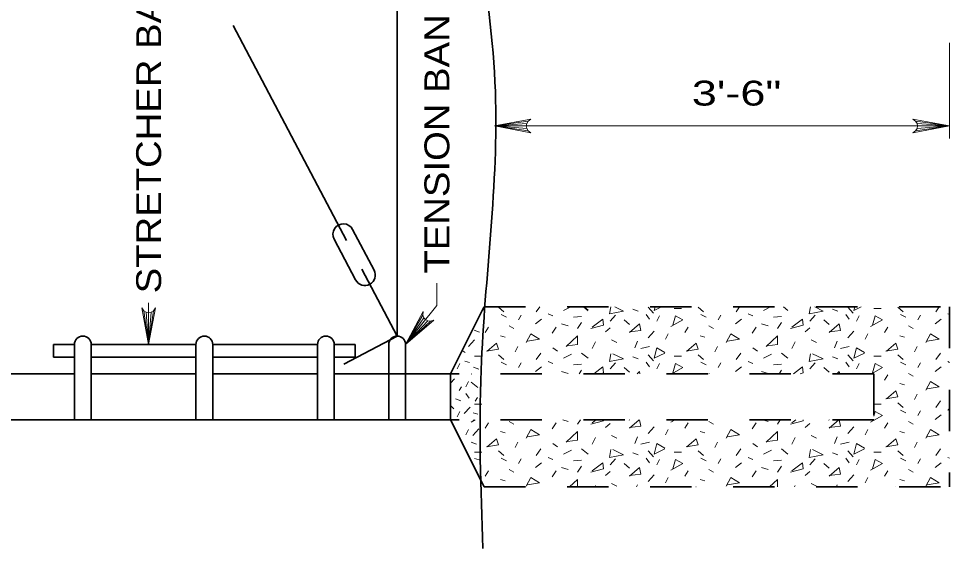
# Model space of a CAD drawing. Extents: x -46.1 to -39.3, y 101.7 to 111.8.
# Drawn here: x -44.121 to -41.878, y 103.825 to 105.103 of the extents above; entities that cross this region are included whole.
import ezdxf
from ezdxf.enums import TextEntityAlignment as Align

# ---------------------------------------------------------------- set-up
doc = ezdxf.new("R2010")
doc.units = 0
doc.header["$LTSCALE"] = 0.024
doc.linetypes.add('SHORT_DASHED', pattern=[2.7, 1.5, -1.2])
for name, color, linetype, lineweight in [('1', 7, 'Continuous', 35), ('10', 7, 'Continuous', 13), ('12', 7, 'Continuous', 53), ('6', 7, 'Continuous', 13)]:
    doc.layers.add(name, color=color, linetype=linetype, lineweight=lineweight)

msp = doc.modelspace()

# ---------------------------------------------------------------- linework, layer by layer
at = {"layer": '1'}
for p, q in [((-43.20892, 104.33669), (-43.20892, 105.15927)), ((-43.33085, 104.5676), (-43.60435, 105.0856)), ((-43.26442, 104.49585), (-43.31629, 104.5941)), ((-43.30906, 104.47227), (-43.36096, 104.57054)), ((-43.20892, 104.33669), (-43.29425, 104.49829)), ((-43.0039, 104.39825), (-43.08015, 104.24577)), ((-42.7594, 104.4074), (-42.74844, 104.39862)), ((-43.20892, 104.33669), (-43.33777, 104.26865)), ((-44.03721, 104.31648), (-44.03721, 104.28617)), ((-43.98671, 104.31648), (-44.03721, 104.31648)), ((-43.98671, 104.13467), (-43.98671, 104.31648)), ((-43.94629, 104.13467), (-43.94629, 104.31648)), ((-43.69377, 104.31648), (-43.94629, 104.31648)), ((-43.69377, 104.13467), (-43.69377, 104.31648)), ((-43.65337, 104.13467), (-43.65337, 104.31648)), ((-43.40083, 104.31648), (-43.65337, 104.31648)), ((-43.40083, 104.13467), (-43.40083, 104.31648)), ((-43.36044, 104.13467), (-43.36044, 104.31648)), ((-43.30994, 104.31648), (-43.36044, 104.31648)), ((-43.30994, 104.31648), (-43.30994, 104.28617)), ((-43.22912, 104.13467), (-43.22912, 104.31648)), ((-43.18873, 104.13467), (-43.18873, 104.31648)), ((-43.98671, 104.28617), (-44.03721, 104.28617)), ((-43.69377, 104.28617), (-43.94629, 104.28617)), ((-43.40083, 104.28617), (-43.65337, 104.28617)), ((-43.30994, 104.28617), (-43.36044, 104.28617)), ((-44.1761, 104.24577), (-43.98671, 104.24577)), ((-43.94629, 104.24577), (-43.69377, 104.24577)), ((-43.65337, 104.24577), (-43.40083, 104.24577)), ((-43.36044, 104.24577), (-43.08015, 104.24577)), ((-43.08015, 104.13467), (-43.08015, 104.24577)), ((-41.88196, 104.15954), (-41.87812, 104.1579)), ((-45.05994, 104.13467), (-43.08015, 104.13467)), ((-43.08015, 104.13467), (-43.00408, 103.98256))]:
    msp.add_line(p, q, dxfattribs=at)
at = {"layer": '1', "linetype": 'SHORT_DASHED'}
for p, q in [((-42.99933, 104.4074), (-43.0039, 104.39825)), ((-42.99933, 104.4074), (-41.87812, 104.4074)), ((-41.87812, 104.4074), (-41.87812, 103.97304)), ((-42.05994, 104.24577), (-43.08015, 104.24577)), ((-42.05994, 104.24577), (-42.05994, 104.13467)), ((-42.05994, 104.13467), (-43.08015, 104.13467)), ((-43.00408, 103.98256), (-42.99933, 103.97304)), ((-42.99933, 103.97304), (-41.87812, 103.97304))]:
    msp.add_line(p, q, dxfattribs=at)
at = {"layer": '1'}
for centre, radius, start, end in [((-43.33862, 104.58232), 0.02525, 27.83223, 207.83416), ((-43.28674, 104.48406), 0.02525, 207.83349, 27.83289), ((-43.9665, 104.31648), 0.0202, 0, 180), ((-43.67357, 104.31648), 0.0202, 0, 180), ((-43.38064, 104.31648), 0.0202, 0, 180), ((-43.20893, 104.31648), 0.0202, 0, 180)]:
    msp.add_arc(centre, radius, start, end, dxfattribs=at)
msp.add_spline([(-42.99933, 111.7931), (-43.04115, 111.45546), (-42.93785, 111.16262), (-43.02392, 110.54252), (-42.95506, 110.00852), (-43.02392, 109.56067), (-42.97227, 109.0439), (-43.04115, 108.68217), (-42.95506, 108.18263), (-43.04115, 107.1491), (-42.97227, 106.47729), (-43.04115, 105.66771), (-42.97227, 104.927), (-43.00671, 104.25521), (-43.00256, 103.82462)], degree=3, dxfattribs=at)
at = {"layer": '10'}
for p, q in [((-41.87812, 105.04375), (-41.87812, 104.81323)), ((-41.87812, 104.84354), (-42.97477, 104.84354)), ((-43.80787, 104.31648), (-43.80787, 104.41715))]:
    msp.add_line(p, q, dxfattribs=at)
for points in [[(-42.97477, 104.84354), (-42.8865, 104.86008), (-42.89331, 104.85537), (-42.89681, 104.84946), (-42.89783, 104.84354), (-42.89681, 104.8376), (-42.89331, 104.83169), (-42.8865, 104.82698), (-42.97477, 104.84354), (-42.89331, 104.83169), (-42.89681, 104.8376), (-42.97477, 104.84354), (-42.89783, 104.84354), (-42.89681, 104.84946), (-42.97477, 104.84354), (-42.89331, 104.85537)], [(-41.87812, 104.84354), (-41.96637, 104.82698), (-41.95958, 104.83169), (-41.95606, 104.8376), (-41.95506, 104.84354), (-41.95606, 104.84946), (-41.95958, 104.85537), (-41.96637, 104.86008), (-41.87812, 104.84354), (-41.95958, 104.85537), (-41.95606, 104.84946), (-41.87812, 104.84354), (-41.95506, 104.84354), (-41.95606, 104.8376), (-41.87812, 104.84354), (-41.95958, 104.83169)], [(-43.18873, 104.31648), (-43.11325, 104.41079), (-43.11325, 104.46473)], [(-43.80787, 104.31648), (-43.82442, 104.40475), (-43.81971, 104.39794), (-43.81379, 104.39444), (-43.80787, 104.39342), (-43.80196, 104.39444), (-43.79604, 104.39794), (-43.79133, 104.40475), (-43.80787, 104.31648), (-43.79604, 104.39794), (-43.80196, 104.39444), (-43.80787, 104.31648), (-43.80787, 104.39342), (-43.81379, 104.39444), (-43.80787, 104.31648), (-43.81971, 104.39794)], [(-43.18873, 104.31648), (-43.1465, 104.39573), (-43.14706, 104.38748), (-43.14465, 104.38104), (-43.14065, 104.37656), (-43.1354, 104.37365), (-43.12858, 104.37269), (-43.12065, 104.37506), (-43.18873, 104.31648), (-43.12858, 104.37269), (-43.1354, 104.37365), (-43.18873, 104.31648), (-43.14065, 104.37656), (-43.14465, 104.38104), (-43.18873, 104.31648), (-43.14706, 104.38748)]]:
    msp.add_lwpolyline(points, dxfattribs=at)
at = {"layer": '6'}
for p, q in [((-42.96506, 104.40665), (-42.95223, 104.39542)), ((-42.86521, 104.4074), (-42.8736, 104.39542)), ((-42.79029, 104.4074), (-42.80781, 104.39862)), ((-42.64094, 104.40183), (-42.6281, 104.39702)), ((-42.60402, 104.40665), (-42.59119, 104.39221)), ((-42.54144, 104.40344), (-42.52379, 104.40344)), ((-42.48369, 104.40665), (-42.47085, 104.39542)), ((-42.38383, 104.4074), (-42.39223, 104.39542)), ((-42.30892, 104.4074), (-42.32644, 104.39862)), ((-42.27802, 104.4074), (-42.26706, 104.39862)), ((-42.15956, 104.40183), (-42.14671, 104.39702)), ((-42.12265, 104.40665), (-42.10981, 104.39221)), ((-42.06006, 104.40344), (-42.04242, 104.40344)), ((-42.00231, 104.40665), (-41.98948, 104.39542)), ((-41.90246, 104.4074), (-41.91085, 104.39542)), ((-42.95865, 104.389), (-42.94581, 104.38258)), ((-42.91692, 104.37617), (-42.9105, 104.3874)), ((-42.86075, 104.37777), (-42.87521, 104.36654)), ((-42.84471, 104.3906), (-42.83348, 104.38579)), ((-42.78375, 104.38258), (-42.76448, 104.38419)), ((-42.69548, 104.37296), (-42.68265, 104.3874)), ((-42.66179, 104.37617), (-42.64896, 104.36494)), ((-42.60883, 104.389), (-42.60081, 104.37777)), ((-42.57675, 104.38579), (-42.58317, 104.37296)), ((-42.47727, 104.389), (-42.46442, 104.38258)), ((-42.43554, 104.37617), (-42.42912, 104.3874)), ((-42.37937, 104.37777), (-42.39383, 104.36654)), ((-42.36333, 104.3906), (-42.3521, 104.38579)), ((-42.30235, 104.38258), (-42.2831, 104.38419)), ((-42.2141, 104.37296), (-42.20127, 104.3874)), ((-42.18042, 104.37617), (-42.16758, 104.36494)), ((-42.12746, 104.389), (-42.11944, 104.37777)), ((-42.09537, 104.38579), (-42.10179, 104.37296)), ((-41.9959, 104.389), (-41.98304, 104.38258)), ((-41.95417, 104.37617), (-41.94775, 104.3874)), ((-41.898, 104.37777), (-41.91246, 104.36654)), ((-41.88196, 104.3906), (-41.87812, 104.38896)), ((-43.02358, 104.35121), (-43.01075, 104.3464)), ((-42.99715, 104.34567), (-42.98913, 104.35852)), ((-42.93937, 104.36173), (-42.92815, 104.35531)), ((-42.82546, 104.35852), (-42.83508, 104.34406)), ((-42.81262, 104.36654), (-42.79658, 104.36173)), ((-42.7741, 104.35531), (-42.76448, 104.36975)), ((-42.70673, 104.34727), (-42.69548, 104.35692)), ((-42.51577, 104.34567), (-42.50775, 104.35852)), ((-42.458, 104.36173), (-42.44677, 104.35531)), ((-42.34408, 104.35852), (-42.35371, 104.34406)), ((-42.33125, 104.36654), (-42.31521, 104.36173)), ((-42.29273, 104.35531), (-42.2831, 104.36975)), ((-42.22533, 104.34727), (-42.2141, 104.35692)), ((-42.0344, 104.34567), (-42.02638, 104.35852)), ((-41.97662, 104.36173), (-41.9654, 104.35531)), ((-42.96025, 104.33765), (-42.94902, 104.33444)), ((-42.58958, 104.3489), (-42.60402, 104.33283)), ((-42.5559, 104.34246), (-42.56231, 104.32962)), ((-42.47887, 104.33765), (-42.46765, 104.33444)), ((-42.10821, 104.3489), (-42.12265, 104.33283)), ((-42.07452, 104.34246), (-42.08094, 104.32962)), ((-41.9975, 104.33765), (-41.98625, 104.33444)), ((-43.02271, 104.32775), (-43.03717, 104.31171)), ((-42.92494, 104.29915), (-42.91852, 104.31198)), ((-42.83348, 104.30877), (-42.82225, 104.30075)), ((-42.73881, 104.30717), (-42.73079, 104.32321)), ((-42.69227, 104.32802), (-42.67944, 104.3216)), ((-42.62971, 104.32481), (-42.63612, 104.30877)), ((-42.60081, 104.31198), (-42.62167, 104.30717)), ((-42.44356, 104.29915), (-42.43715, 104.31198)), ((-42.3521, 104.30877), (-42.34087, 104.30075)), ((-42.25744, 104.30717), (-42.24942, 104.32321)), ((-42.2109, 104.32802), (-42.19806, 104.3216)), ((-42.14831, 104.32481), (-42.15475, 104.30877)), ((-42.11944, 104.31198), (-42.14029, 104.30717)), ((-41.96219, 104.29915), (-41.95577, 104.31198)), ((-43.05223, 104.30158), (-43.04529, 104.29754)), ((-43.02283, 104.28792), (-43.00517, 104.28792)), ((-42.96506, 104.29112), (-42.95223, 104.2799)), ((-42.86235, 104.29594), (-42.8736, 104.2799)), ((-42.78856, 104.29273), (-42.80781, 104.2831)), ((-42.76448, 104.29594), (-42.74844, 104.2831)), ((-42.64094, 104.28631), (-42.6281, 104.2815)), ((-42.60402, 104.29112), (-42.59119, 104.27669)), ((-42.54144, 104.28792), (-42.52379, 104.28792)), ((-42.48369, 104.29112), (-42.47085, 104.2799)), ((-42.38098, 104.29594), (-42.39223, 104.2799)), ((-42.30719, 104.29273), (-42.32644, 104.2831)), ((-42.2831, 104.29594), (-42.26706, 104.2831)), ((-42.15956, 104.28631), (-42.14671, 104.2815)), ((-42.12265, 104.29112), (-42.10981, 104.27669)), ((-42.06006, 104.28792), (-42.04242, 104.28792)), ((-42.00231, 104.29112), (-41.98948, 104.2799)), ((-41.8996, 104.29594), (-41.91085, 104.2799)), ((-43.05812, 104.27027), (-43.06454, 104.25742)), ((-43.04581, 104.27646), (-43.03458, 104.27325)), ((-43.02477, 104.26196), (-43.01192, 104.25715)), ((-42.95865, 104.27348), (-42.94581, 104.26704)), ((-42.91692, 104.26062), (-42.9105, 104.27187)), ((-42.86075, 104.26223), (-42.87521, 104.251)), ((-42.84471, 104.27508), (-42.83348, 104.27027)), ((-42.78375, 104.26704), (-42.76448, 104.26867)), ((-42.69548, 104.25742), (-42.68265, 104.27187)), ((-42.60883, 104.27348), (-42.60081, 104.26223)), ((-42.57675, 104.27027), (-42.58317, 104.25742)), ((-42.47727, 104.27348), (-42.46442, 104.26704)), ((-42.43554, 104.26062), (-42.42912, 104.27187)), ((-42.37937, 104.26223), (-42.39383, 104.251)), ((-42.36333, 104.27508), (-42.3521, 104.27027)), ((-42.30235, 104.26704), (-42.2831, 104.26867)), ((-42.2141, 104.25742), (-42.20127, 104.27187)), ((-42.12746, 104.27348), (-42.11944, 104.26223)), ((-42.09537, 104.27027), (-42.10179, 104.25742)), ((-41.9959, 104.27348), (-41.98304, 104.26704)), ((-41.95417, 104.26062), (-41.94775, 104.27187)), ((-41.898, 104.26223), (-41.91246, 104.251)), ((-41.88196, 104.27508), (-41.87812, 104.27342)), ((-43.03085, 104.24458), (-43.02871, 104.24577)), ((-42.93937, 104.24619), (-42.93865, 104.24577)), ((-42.81262, 104.251), (-42.79658, 104.24619)), ((-42.7701, 104.24577), (-42.76448, 104.25421)), ((-42.66179, 104.26062), (-42.64896, 104.2494)), ((-42.458, 104.24619), (-42.45727, 104.24577)), ((-42.33125, 104.251), (-42.31521, 104.24619)), ((-42.28873, 104.24577), (-42.2831, 104.25421)), ((-42.18042, 104.26062), (-42.16758, 104.2494)), ((-42.0344, 104.23015), (-42.02638, 104.24298)), ((-41.97662, 104.24619), (-41.9654, 104.23977)), ((-43.07096, 104.23335), (-43.08015, 104.22317)), ((-43.03727, 104.22694), (-43.04369, 104.2141)), ((-43.03094, 104.22546), (-43.0149, 104.21263)), ((-41.9975, 104.22212), (-41.98625, 104.21892)), ((-43.05992, 104.20583), (-43.05429, 104.21429)), ((-43.04315, 104.1986), (-43.03513, 104.18738)), ((-41.96219, 104.1836), (-41.95577, 104.19646)), ((-43.06819, 104.1856), (-43.05535, 104.18079)), ((-43.02283, 104.17238), (-43.00517, 104.17238)), ((-43.02119, 104.18), (-43.01556, 104.18844)), ((-42.06006, 104.17238), (-42.05994, 104.17238)), ((-42.05994, 104.17238), (-42.04242, 104.17238)), ((-42.00231, 104.17558), (-41.98948, 104.16435)), ((-41.8996, 104.1804), (-41.91085, 104.16435)), ((-43.08015, 104.16967), (-43.07256, 104.16115)), ((-43.05812, 104.15473), (-43.06454, 104.1419)), ((-43.03327, 104.16567), (-43.04773, 104.14963)), ((-43.02585, 104.15196), (-43.01462, 104.14875)), ((-41.9959, 104.15794), (-41.98304, 104.15152)), ((-41.95417, 104.1451), (-41.94775, 104.15633)), ((-43.03085, 104.12906), (-43.02075, 104.13467)), ((-43.02535, 104.13467), (-43.02604, 104.13227)), ((-42.99715, 104.11462), (-42.98913, 104.12746)), ((-42.93937, 104.13067), (-42.92815, 104.12425)), ((-42.82546, 104.12746), (-42.83508, 104.11302)), ((-42.80992, 104.13467), (-42.79658, 104.13067)), ((-42.7741, 104.12425), (-42.76717, 104.13467)), ((-42.72921, 104.13467), (-42.73881, 104.12746)), ((-42.64985, 104.13467), (-42.64896, 104.13388)), ((-42.62583, 104.13467), (-42.64896, 104.11462)), ((-42.54948, 104.12906), (-42.53937, 104.13467)), ((-42.54398, 104.13467), (-42.54467, 104.13227)), ((-42.51577, 104.11462), (-42.50775, 104.12746)), ((-42.458, 104.13067), (-42.44677, 104.12425)), ((-42.34408, 104.12746), (-42.35371, 104.11302)), ((-42.32854, 104.13467), (-42.31521, 104.13067)), ((-42.29273, 104.12425), (-42.28579, 104.13467)), ((-42.24783, 104.13467), (-42.25744, 104.12746)), ((-42.16848, 104.13467), (-42.16758, 104.13388)), ((-42.14444, 104.13467), (-42.16758, 104.11462)), ((-42.0626, 104.13467), (-42.06327, 104.13227)), ((-42.0344, 104.11462), (-42.02638, 104.12746)), ((-41.97662, 104.13067), (-41.9654, 104.12425)), ((-41.898, 104.14671), (-41.91246, 104.13548)), ((-43.07096, 104.11783), (-43.07144, 104.11729)), ((-43.03727, 104.11142), (-43.04369, 104.09856)), ((-43.01215, 104.11281), (-43.02658, 104.09677)), ((-42.96025, 104.10658), (-42.94902, 104.10337)), ((-42.70673, 104.11623), (-42.69548, 104.12585)), ((-42.58958, 104.11783), (-42.60402, 104.10177)), ((-42.5559, 104.11142), (-42.56231, 104.09856)), ((-42.47887, 104.10658), (-42.46765, 104.10337)), ((-42.22533, 104.11623), (-42.2141, 104.12585)), ((-42.10821, 104.11783), (-42.12265, 104.10177)), ((-42.07452, 104.11142), (-42.08094, 104.09856)), ((-41.9975, 104.10658), (-41.98625, 104.10337)), ((-42.73881, 104.0761), (-42.73079, 104.09215)), ((-42.69227, 104.09696), (-42.67944, 104.09054)), ((-42.62971, 104.09375), (-42.63612, 104.07771)), ((-42.25744, 104.0761), (-42.24942, 104.09215)), ((-42.2109, 104.09696), (-42.19806, 104.09054)), ((-42.14831, 104.09375), (-42.15475, 104.07771)), ((-43.04635, 104.0671), (-43.04529, 104.06648)), ((-43.03063, 104.08108), (-43.01779, 104.07627)), ((-42.96506, 104.06006), (-42.95223, 104.04883)), ((-42.92494, 104.06808), (-42.91852, 104.08092)), ((-42.86235, 104.06488), (-42.8736, 104.04883)), ((-42.83348, 104.07771), (-42.82225, 104.06969)), ((-42.78856, 104.06167), (-42.80781, 104.05204)), ((-42.76448, 104.06488), (-42.74844, 104.05204)), ((-42.60081, 104.08092), (-42.62167, 104.0761)), ((-42.60402, 104.06006), (-42.59119, 104.04563)), ((-42.48369, 104.06006), (-42.47085, 104.04883)), ((-42.44356, 104.06808), (-42.43715, 104.08092)), ((-42.38098, 104.06488), (-42.39223, 104.04883)), ((-42.3521, 104.07771), (-42.34087, 104.06969)), ((-42.30719, 104.06167), (-42.32644, 104.05204)), ((-42.2831, 104.06488), (-42.26706, 104.05204)), ((-42.11944, 104.08092), (-42.14029, 104.0761)), ((-42.12265, 104.06006), (-42.10981, 104.04563)), ((-42.00231, 104.06006), (-41.98948, 104.04883)), ((-41.96219, 104.06808), (-41.95577, 104.08092)), ((-41.8996, 104.06488), (-41.91085, 104.04883)), ((-43.02283, 104.05685), (-43.00517, 104.05685)), ((-43.02233, 104.04156), (-43.0111, 104.03835)), ((-42.95865, 104.04242), (-42.94581, 104.036)), ((-42.91692, 104.02956), (-42.9105, 104.04081)), ((-42.84471, 104.04402), (-42.83348, 104.03921)), ((-42.78375, 104.036), (-42.76448, 104.0376)), ((-42.69548, 104.02635), (-42.68265, 104.04081)), ((-42.64094, 104.05525), (-42.6281, 104.05044)), ((-42.60883, 104.04242), (-42.60081, 104.03119)), ((-42.57675, 104.03921), (-42.58317, 104.02635)), ((-42.54144, 104.05685), (-42.52379, 104.05685)), ((-42.47727, 104.04242), (-42.46442, 104.036)), ((-42.43554, 104.02956), (-42.42912, 104.04081)), ((-42.36333, 104.04402), (-42.3521, 104.03921)), ((-42.30235, 104.036), (-42.2831, 104.0376)), ((-42.2141, 104.02635), (-42.20127, 104.04081)), ((-42.15956, 104.05525), (-42.14671, 104.05044)), ((-42.12746, 104.04242), (-42.11944, 104.03119)), ((-42.09537, 104.03921), (-42.10179, 104.02635)), ((-42.06006, 104.05685), (-42.04242, 104.05685)), ((-41.9959, 104.04242), (-41.98304, 104.036)), ((-41.95417, 104.02956), (-41.94775, 104.04081)), ((-41.88196, 104.04402), (-41.87812, 104.04237)), ((-42.93937, 104.01512), (-42.92815, 104.00871)), ((-42.86075, 104.03119), (-42.87521, 104.01994)), ((-42.81262, 104.01994), (-42.79658, 104.01512)), ((-42.7741, 104.00871), (-42.76448, 104.02315)), ((-42.66179, 104.02956), (-42.64896, 104.01833)), ((-42.458, 104.01512), (-42.44677, 104.00871)), ((-42.37937, 104.03119), (-42.39383, 104.01994)), ((-42.33125, 104.01994), (-42.31521, 104.01512)), ((-42.29273, 104.00871), (-42.2831, 104.02315)), ((-42.18042, 104.02956), (-42.16758, 104.01833)), ((-41.97662, 104.01512), (-41.9654, 104.00871)), ((-41.898, 104.03119), (-41.91246, 104.01994)), ((-42.99715, 103.99908), (-42.98913, 104.01192)), ((-42.82546, 104.01192), (-42.83508, 103.99748)), ((-42.70673, 104.00069), (-42.69548, 104.01031)), ((-42.58958, 104.00229), (-42.60402, 103.98625)), ((-42.5559, 103.99587), (-42.56231, 103.98304)), ((-42.51577, 103.99908), (-42.50775, 104.01192)), ((-42.34408, 104.01192), (-42.35371, 103.99748)), ((-42.22533, 104.00069), (-42.2141, 104.01031)), ((-42.10821, 104.00229), (-42.12265, 103.98625)), ((-42.07452, 103.99587), (-42.08094, 103.98304)), ((-42.0344, 103.99908), (-42.02638, 104.01192)), ((-42.96025, 103.99106), (-42.94902, 103.98785)), ((-42.73258, 103.97304), (-42.73079, 103.97662)), ((-42.69227, 103.98144), (-42.67944, 103.97502)), ((-42.62971, 103.97823), (-42.63177, 103.97304)), ((-42.47887, 103.99106), (-42.46765, 103.98785)), ((-42.25121, 103.97304), (-42.24942, 103.97662)), ((-42.2109, 103.98144), (-42.19806, 103.97502)), ((-42.14831, 103.97823), (-42.1504, 103.97304)), ((-41.9975, 103.99106), (-41.98625, 103.98785))]:
    msp.add_line(p, q, dxfattribs=at)
for points in [[(-42.69429, 104.4074), (-42.69708, 104.3906), (-42.6634, 104.39702), (-42.68413, 104.4074)], [(-42.57206, 104.4074), (-42.58958, 104.39862), (-42.5874, 104.4074)], [(-42.21292, 104.4074), (-42.21571, 104.3906), (-42.18202, 104.39702), (-42.20275, 104.4074)], [(-42.09069, 104.4074), (-42.10821, 104.39862), (-42.10602, 104.4074)], [(-42.74202, 104.35531), (-42.71154, 104.36333), (-42.71315, 104.37777), (-42.73881, 104.35852)], [(-42.54948, 104.36012), (-42.52058, 104.37617), (-42.53823, 104.38579), (-42.54467, 104.36333)], [(-42.26065, 104.35531), (-42.23017, 104.36333), (-42.23177, 104.37777), (-42.25744, 104.35852)], [(-42.0681, 104.36012), (-42.03921, 104.37617), (-42.05685, 104.38579), (-42.06327, 104.36333)], [(-42.64896, 104.34727), (-42.62167, 104.3505), (-42.62487, 104.36654), (-42.64896, 104.34567)], [(-42.16758, 104.34727), (-42.14029, 104.3505), (-42.1435, 104.36654), (-42.16758, 104.34567)], [(-42.89767, 104.3216), (-42.88644, 104.34246), (-42.86558, 104.32962), (-42.89446, 104.32481)], [(-42.79819, 104.31358), (-42.7741, 104.31679), (-42.7741, 104.33765), (-42.8014, 104.31198)], [(-42.41629, 104.3216), (-42.40506, 104.34246), (-42.38419, 104.32962), (-42.41308, 104.32481)], [(-42.31681, 104.31358), (-42.29273, 104.31679), (-42.29273, 104.33765), (-42.32002, 104.31198)], [(-41.93492, 104.3216), (-41.92369, 104.34246), (-41.90281, 104.32962), (-41.93171, 104.32481)], [(-42.99394, 104.30075), (-42.96506, 104.30556), (-42.96988, 104.32), (-42.99233, 104.30075)], [(-42.56392, 104.29594), (-42.58958, 104.2831), (-42.58317, 104.30877), (-42.56392, 104.29754)], [(-42.51256, 104.30075), (-42.48369, 104.30556), (-42.4885, 104.32), (-42.51096, 104.30075)], [(-42.08254, 104.29594), (-42.10821, 104.2831), (-42.10179, 104.30877), (-42.08254, 104.29754)], [(-42.03119, 104.30075), (-42.00231, 104.30556), (-42.00713, 104.32), (-42.02958, 104.30075)], [(-42.69387, 104.29433), (-42.69708, 104.27508), (-42.6634, 104.2815), (-42.68906, 104.29433)], [(-42.2125, 104.29433), (-42.21571, 104.27508), (-42.18202, 104.2815), (-42.20769, 104.29433)], [(-42.71923, 104.24577), (-42.71154, 104.24779), (-42.71315, 104.26223), (-42.73508, 104.24577)], [(-42.54733, 104.24577), (-42.52058, 104.26062), (-42.53823, 104.27027), (-42.54467, 104.24779)], [(-42.23785, 104.24577), (-42.23017, 104.24779), (-42.23177, 104.26223), (-42.25371, 104.24577)], [(-42.06596, 104.24577), (-42.03921, 104.26062), (-42.05685, 104.27027), (-42.06327, 104.24779)], [(-42.62383, 104.24577), (-42.62487, 104.251), (-42.63092, 104.24577)], [(-42.14246, 104.24577), (-42.1435, 104.251), (-42.14954, 104.24577)], [(-41.93492, 104.20608), (-41.92369, 104.22694), (-41.90281, 104.2141), (-41.93171, 104.20929)], [(-42.03119, 104.18521), (-42.00231, 104.19004), (-42.00713, 104.20448), (-42.02958, 104.18521)], [(-42.0681, 104.12906), (-42.03921, 104.1451), (-42.05685, 104.15473), (-42.05994, 104.14398)], [(-42.74202, 104.12425), (-42.71154, 104.13227), (-42.71179, 104.13467)], [(-42.64896, 104.11623), (-42.62167, 104.11944), (-42.62473, 104.13467)], [(-42.26065, 104.12425), (-42.23017, 104.13227), (-42.23042, 104.13467)], [(-42.16758, 104.11623), (-42.14029, 104.11944), (-42.14335, 104.13467)], [(-42.89767, 104.09054), (-42.88644, 104.11142), (-42.86558, 104.09856), (-42.89446, 104.09375)], [(-42.79819, 104.08252), (-42.7741, 104.08573), (-42.7741, 104.10658), (-42.8014, 104.08092)], [(-42.41629, 104.09054), (-42.40506, 104.11142), (-42.38419, 104.09856), (-42.41308, 104.09375)], [(-42.31681, 104.08252), (-42.29273, 104.08573), (-42.29273, 104.10658), (-42.32002, 104.08092)], [(-41.93492, 104.09054), (-41.92369, 104.11142), (-41.90281, 104.09856), (-41.93171, 104.09375)], [(-42.99394, 104.06969), (-42.96506, 104.0745), (-42.96988, 104.08894), (-42.99233, 104.06969)], [(-42.51256, 104.06969), (-42.48369, 104.0745), (-42.4885, 104.08894), (-42.51096, 104.06969)], [(-42.03119, 104.06969), (-42.00231, 104.0745), (-42.00713, 104.08894), (-42.02958, 104.06969)], [(-42.69387, 104.06327), (-42.69708, 104.04402), (-42.6634, 104.05044), (-42.68906, 104.06327)], [(-42.56392, 104.06488), (-42.58958, 104.05204), (-42.58317, 104.07771), (-42.56392, 104.06648)], [(-42.2125, 104.06327), (-42.21571, 104.04402), (-42.18202, 104.05044), (-42.20769, 104.06327)], [(-42.08254, 104.06488), (-42.10821, 104.05204), (-42.10179, 104.07771), (-42.08254, 104.06648)], [(-42.54948, 104.01352), (-42.52058, 104.02956), (-42.53823, 104.03921), (-42.54467, 104.01673)], [(-42.0681, 104.01352), (-42.03921, 104.02956), (-42.05685, 104.03921), (-42.06327, 104.01673)], [(-42.74202, 104.00871), (-42.71154, 104.01673), (-42.71315, 104.03119), (-42.73881, 104.01192)], [(-42.64896, 104.00069), (-42.62167, 104.0039), (-42.62487, 104.01994), (-42.64896, 103.99908)], [(-42.26065, 104.00871), (-42.23017, 104.01673), (-42.23177, 104.03119), (-42.25744, 104.01192)], [(-42.16758, 104.00069), (-42.14029, 104.0039), (-42.1435, 104.01994), (-42.16758, 103.99908)], [(-42.89767, 103.97502), (-42.88644, 103.99587), (-42.86558, 103.98304), (-42.89446, 103.97823)], [(-42.41629, 103.97502), (-42.40506, 103.99587), (-42.38419, 103.98304), (-42.41308, 103.97823)], [(-41.93492, 103.97502), (-41.92369, 103.99587), (-41.90281, 103.98304), (-41.93171, 103.97823)], [(-42.96975, 103.97304), (-42.96988, 103.97342), (-42.97029, 103.97304)], [(-42.7741, 103.97304), (-42.7741, 103.99106), (-42.79325, 103.97304)], [(-42.48837, 103.97304), (-42.4885, 103.97342), (-42.48892, 103.97304)], [(-42.29273, 103.97304), (-42.29273, 103.99106), (-42.31188, 103.97304)], [(-42.007, 103.97304), (-42.00713, 103.97342), (-42.00754, 103.97304)]]:
    msp.add_lwpolyline(points, dxfattribs=at)

# ---------------------------------------------------------------- texts
at = {"layer": '12', "width": 1.15}
for s, p in [('STRETCHER BAR', (-43.77788, 104.43984)), ('TENSION BAND', (-43.08325, 104.48745))]:
    msp.add_text(s, height=0.06, rotation=90, dxfattribs=at).set_placement(p)
at = {"layer": '12', "width": 1.35}
msp.add_text('3\'-6"', height=0.06, dxfattribs=at).set_placement((-42.39094, 104.89278), align=Align.CENTER)

doc.saveas('drawing.dxf')
